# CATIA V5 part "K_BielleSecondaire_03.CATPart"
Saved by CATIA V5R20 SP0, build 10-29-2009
Part number: Bielle_secondaire_03
Bounding box of the stored display mesh (mm): x -415 to 15, y -279.606 to -264.606, z 108.626 to 189.527
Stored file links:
  G:\Khaled_CFAO_2011\ST2M\ST2M_GR2\jcoetard\Khaled\CAD_CATIA\K_BielleSecondaire_03.CATPart
  J:\Thinkmotion\Thinkmotion_COETARD\Maquette_catia\Maquette_catia_R20_Licence_education\jcharlescoetard.CATPRODUCT\Assemblage_Pince_Prehension_Mors_Paralleles.CATProduct
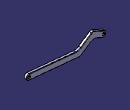
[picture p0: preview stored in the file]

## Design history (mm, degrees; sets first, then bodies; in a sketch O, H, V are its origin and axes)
Set1
  Plane1 "Plan_bielle_secondaire_03": linked copy from another document
  Point1: linked copy from another document
  Point2: linked copy from another document
Body1 (main body)
  Sketch1 on Plane1, origin (0, -279.606, 0), H (-1, 0, 0), V (0, 0, 1)
    construction line L1 (0, 150) -> (271.0207, 123.6257)
    point P2 (271.0207, 123.6257)
    line L2 (1.4529, 164.9295) -> (252.5486, 140.4941)
    line L3 (269.5678, 108.6962) -> (-1.4529, 135.0705)
    arc A1 centre (0, 150) radius 15 from (-1.4529, 135.0705) to (1.4529, 164.9295) cw
    construction line L4 (271.0207, 123.6257) -> (345.2427, 174.5284)
    point P6 (271.0207, 123.6257)
    point P7 (345.2427, 174.5284)
    line L5 (279.0464, 147.3185) -> (336.7589, 186.8987)
    line L6 (328.287, 144.7112) -> (279.5045, 111.2553)
    arc A2 centre (345.2427, 174.5284) radius 15 from (336.7589, 186.8987) to (351.3748, 188.2177) cw
    arc A3 centre (271.0207, 123.6257) radius 15 from (279.5045, 111.2553) to (269.5678, 108.6962) cw
    reference projected point E1 (0, 150) from Point1
    construction line L7 (345.2427, 174.5284) -> (400, 150)
    point P10 (345.2427, 174.5284)
    line L8 (351.3748, 188.2177) -> (406.1321, 163.6893)
    line L9 (393.8679, 136.3107) -> (367.2626, 148.2284)
    arc A4 centre (400, 150) radius 15 from (406.1321, 163.6893) to (393.8679, 136.3107) cw
    reference projected point E2 (400, 150) from Point2
    arc A5 centre (350.9104, 111.7236) radius 40 from (328.287, 144.7112) to (367.2626, 148.2284) cw
    point P17 (350.9104, 111.7236)
    arc A6 centre (256.4229, 180.3061) radius 40 from (252.5486, 140.4941) to (279.0464, 147.3185) ccw
    point P20 (256.4229, 180.3061)
    distance L3 L2 = 30
    distance L5 L6 = 30
    distance L8 L9 = 30
    length L7 = 60
    length L4 = 90
    radius A5 = 40
    radius A6 = 40
    distance P17 P10 = 63.06
    distance P20 P6 = 58.53
    tangency: A1 L2, A1 L3, A2 L5, A3 L5, A2 L6, A3 L6, A4 L8, A4 L9, L3 A3, A2 L8, A5 L6, A5 L9, A6 L2, A6 L5
    coincidence: P6 P2, P10 P7
    concentricity: E1 A1, A4 E2
  Pad1: profile Sketch1, direction (0, 1, 0), length 15
  Sketch2 on end face of Pad1, origin (-400, -264.606, 140), H (1, 0, 0), V (0, 0, -1)
    point P1 (0, -10)
    reference projected point E1 (0, -10) from Point2
    coincidence: E1 P1
  Hole1: placed by Sketch2, at (-400, -264.606, 150) direction (0, -1, 0), diameter 10, depth 20
  Sketch3 on end face of Pad1, origin (0, -264.606, 140), H (1, 0, 0), V (0, 0, -1)
    point P1 (0, -10)
    reference projected point E1 (0, -10) from Point1
    coincidence: E1 P1
  Hole2: placed by Sketch3, at (0, -264.606, 150) direction (0, -1, 0), diameter 10, depth 20
  Fillet1: radius 2, on edge [start face of Pad1 | face of Pad1 from Sketch1.L3]; end face of Pad1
